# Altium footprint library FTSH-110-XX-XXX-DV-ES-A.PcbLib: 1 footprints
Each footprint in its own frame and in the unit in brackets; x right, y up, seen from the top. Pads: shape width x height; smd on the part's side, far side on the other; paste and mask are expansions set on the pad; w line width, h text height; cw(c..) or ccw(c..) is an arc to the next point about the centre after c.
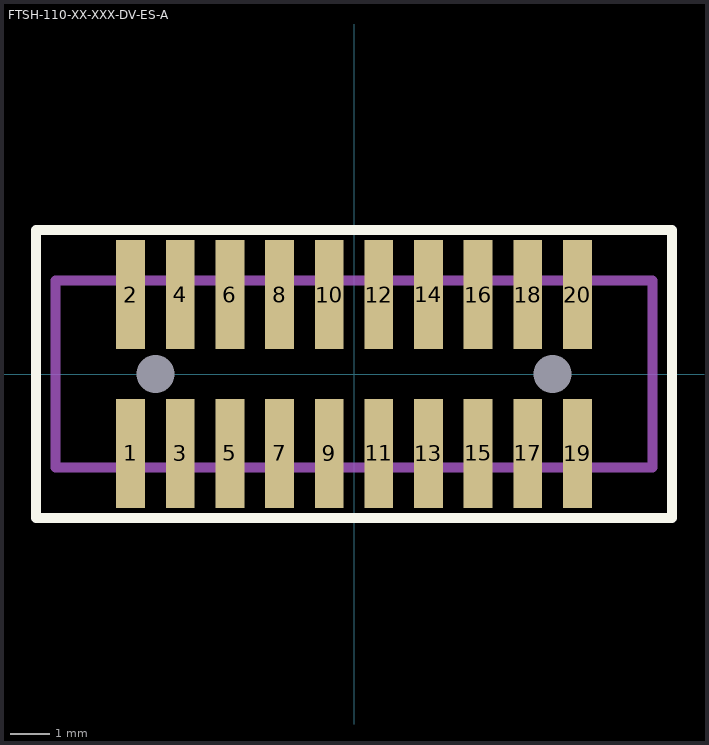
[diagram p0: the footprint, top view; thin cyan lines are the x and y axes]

## FTSH-110-XX-XXX-DV-ES-A [mil]
pads (22):
  rect 29x110 smd mask+2: 1(-225,-80) 2(-225,80) 3(-175,-80) 4(-175,80) 5(-125,-80) 6(-125,80) 7(-75,-80) 8(-75,80) 9(-25,-80) 10(-25,80) 11(25,-80) 12(25,80) 13(75,-80) 14(75,80) 15(125,-80) 16(125,80) 17(175,-80) 18(175,80) 19(225,-80) 20(225,80)
  round 0 hole 38 unplated: 21(-200,0) 22(200,0)
Top Overlay:
  lines w10: -320.5,-145 320.5,-145 320.5,145 -320.5,145 -320.5,-145
Mechanical 1:
  lines w10: -300.5,-94 300.5,-94 300.5,94 -300.5,94 -300.5,-94
  text "J1" at -17.57,-18 h30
